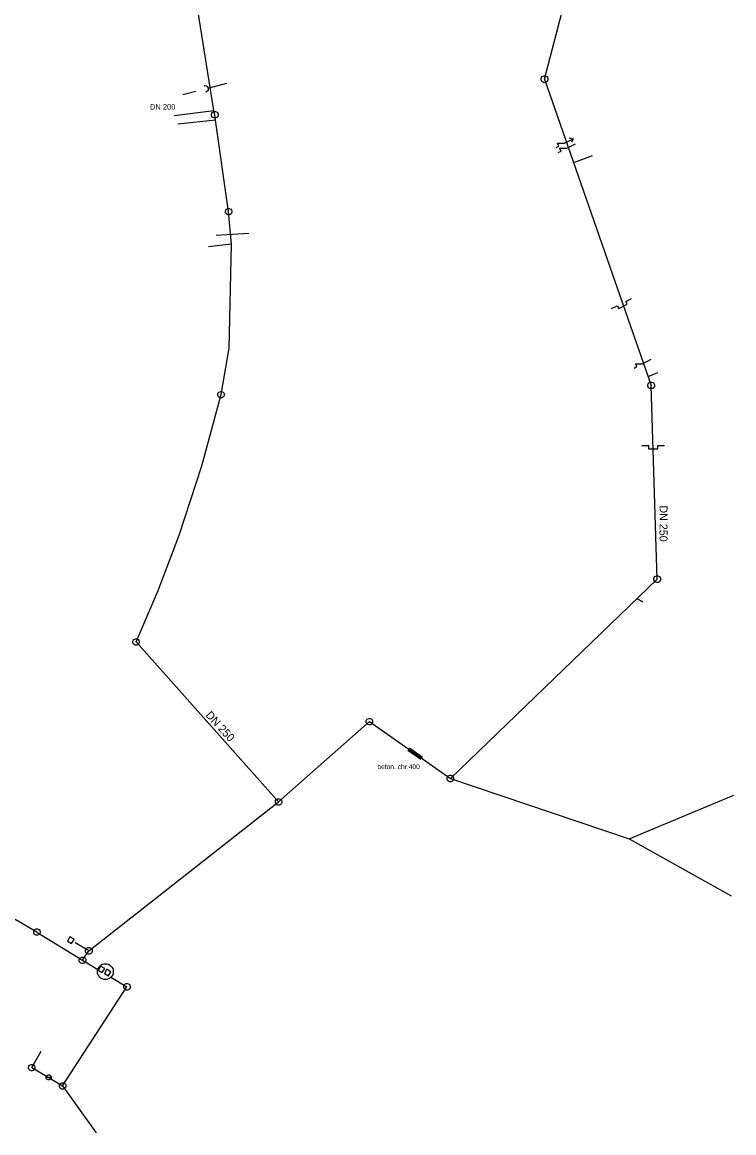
# Model space of a CAD drawing. Extents: x -717256 to -716843, y -1145423 to -1142840.
# Drawn here: x -716986 to -716875, y -1145422.6 to -1145249.2 of the extents above; entities that cross this region are included whole.
import ezdxf

# ---------------------------------------------------------------- set-up
doc = ezdxf.new("R2010")
doc.units = 0
for name, color, linetype in [('Vrstva 29', 7, 'Continuous'), ('Vrstva 30', 7, 'Continuous'), ('Vrstva 31', 7, 'Continuous'), ('Vrstva 9', 7, 'Continuous')]:
    doc.layers.add(name, color=color, linetype=linetype)

msp = doc.modelspace()

# ---------------------------------------------------------------- linework, layer by layer
at = {"layer": 'Vrstva 29'}
for p, q in [((-716923.822, -1145364.386), (-716925.867, -1145362.949)), ((-716925.579, -1145362.539), (-716923.534, -1145363.977))]:
    msp.add_line(p, q, dxfattribs=at)
at = {"layer": 'Vrstva 30'}
for p, q in [((-716956.115, -1145263.016), (-716962.169, -1145225.426)), ((-716904.513, -1145258.142), (-716897.434, -1145230.811)), ((-716905.013, -1145258.042), (-716904.963, -1145257.892)), ((-716905.013, -1145258.242), (-716905.013, -1145258.042)), ((-716904.913, -1145258.492), (-716905.013, -1145258.242)), ((-716904.963, -1145257.892), (-716904.863, -1145257.742)), ((-716904.863, -1145257.742), (-716904.613, -1145257.642)), ((-716904.613, -1145257.642), (-716904.413, -1145257.642)), ((-716904.513, -1145258.142), (-716887.864, -1145305.962)), ((-716904.413, -1145257.642), (-716904.163, -1145257.742)), ((-716904.163, -1145257.742), (-716904.063, -1145257.892)), ((-716904.013, -1145258.242), (-716904.113, -1145258.492)), ((-716904.063, -1145257.892), (-716904.013, -1145258.042)), ((-716904.013, -1145258.042), (-716904.013, -1145258.242)), ((-716904.763, -1145258.592), (-716904.913, -1145258.492)), ((-716904.613, -1145258.642), (-716904.763, -1145258.592)), ((-716904.413, -1145258.642), (-716904.613, -1145258.642)), ((-716904.263, -1145258.592), (-716904.413, -1145258.642)), ((-716904.113, -1145258.492), (-716904.263, -1145258.592)), ((-716956.47, -1145263.599), (-716956.42, -1145263.449)), ((-716956.47, -1145263.799), (-716956.47, -1145263.599)), ((-716956.42, -1145263.449), (-716956.32, -1145263.299)), ((-716956.32, -1145263.299), (-716956.07, -1145263.199)), ((-716955.97, -1145263.699), (-716956.115, -1145263.016)), ((-716956.07, -1145263.199), (-716955.87, -1145263.199)), ((-716955.87, -1145263.199), (-716955.62, -1145263.299)), ((-716955.62, -1145263.299), (-716955.52, -1145263.449)), ((-716955.52, -1145263.449), (-716955.47, -1145263.599)), ((-716955.47, -1145263.599), (-716955.47, -1145263.799)), ((-716956.37, -1145264.049), (-716956.47, -1145263.799)), ((-716956.22, -1145264.149), (-716956.37, -1145264.049)), ((-716956.07, -1145264.199), (-716956.22, -1145264.149)), ((-716955.87, -1145264.199), (-716956.07, -1145264.199)), ((-716955.891, -1145264.537), (-716955.97, -1145263.699)), ((-716953.814, -1145278.818), (-716955.891, -1145264.537)), ((-716955.72, -1145264.149), (-716955.87, -1145264.199)), ((-716955.57, -1145264.049), (-716955.72, -1145264.149)), ((-716955.47, -1145263.799), (-716955.57, -1145264.049)), ((-716954.314, -1145278.718), (-716954.264, -1145278.568)), ((-716954.314, -1145278.918), (-716954.314, -1145278.718)), ((-716954.214, -1145279.168), (-716954.314, -1145278.918)), ((-716954.264, -1145278.568), (-716954.164, -1145278.418)), ((-716954.064, -1145279.268), (-716954.214, -1145279.168)), ((-716954.164, -1145278.418), (-716953.914, -1145278.318)), ((-716953.914, -1145278.318), (-716953.714, -1145278.318)), ((-716953.374, -1145283.917), (-716953.814, -1145278.818)), ((-716953.714, -1145278.318), (-716953.464, -1145278.418)), ((-716953.414, -1145279.168), (-716953.564, -1145279.268)), ((-716953.464, -1145278.418), (-716953.364, -1145278.568)), ((-716953.314, -1145278.918), (-716953.414, -1145279.168)), ((-716953.364, -1145278.568), (-716953.314, -1145278.718)), ((-716953.314, -1145278.718), (-716953.314, -1145278.918)), ((-716953.914, -1145279.318), (-716954.064, -1145279.268)), ((-716953.714, -1145279.318), (-716953.914, -1145279.318)), ((-716953.564, -1145279.268), (-716953.714, -1145279.318)), ((-716953.738, -1145300.138), (-716953.374, -1145283.917)), ((-716954.999, -1145307.385), (-716953.738, -1145300.138)), ((-716955.449, -1145307.135), (-716955.349, -1145306.985)), ((-716955.349, -1145306.985), (-716955.099, -1145306.885)), ((-716955.099, -1145306.885), (-716954.899, -1145306.885)), ((-716954.899, -1145306.885), (-716954.649, -1145306.985)), ((-716954.649, -1145306.985), (-716954.549, -1145307.135)), ((-716888.364, -1145305.862), (-716888.314, -1145305.712)), ((-716888.364, -1145306.062), (-716888.364, -1145305.862)), ((-716888.264, -1145306.312), (-716888.364, -1145306.062)), ((-716888.314, -1145305.712), (-716888.214, -1145305.562)), ((-716888.114, -1145306.412), (-716888.264, -1145306.312)), ((-716888.214, -1145305.562), (-716887.964, -1145305.462)), ((-716887.964, -1145306.462), (-716888.114, -1145306.412)), ((-716887.964, -1145305.462), (-716887.764, -1145305.462)), ((-716887.764, -1145306.462), (-716887.964, -1145306.462)), ((-716886.933, -1145336.203), (-716887.864, -1145305.962)), ((-716887.764, -1145305.462), (-716887.514, -1145305.562)), ((-716887.614, -1145306.412), (-716887.764, -1145306.462)), ((-716887.464, -1145306.312), (-716887.614, -1145306.412)), ((-716887.514, -1145305.562), (-716887.414, -1145305.712)), ((-716887.364, -1145306.062), (-716887.464, -1145306.312)), ((-716887.414, -1145305.712), (-716887.364, -1145305.862)), ((-716887.364, -1145305.862), (-716887.364, -1145306.062)), ((-716957.99, -1145318.53), (-716954.999, -1145307.385)), ((-716955.499, -1145307.285), (-716955.449, -1145307.135)), ((-716955.499, -1145307.485), (-716955.499, -1145307.285)), ((-716955.399, -1145307.735), (-716955.499, -1145307.485)), ((-716955.249, -1145307.835), (-716955.399, -1145307.735)), ((-716955.099, -1145307.885), (-716955.249, -1145307.835)), ((-716954.899, -1145307.885), (-716955.099, -1145307.885)), ((-716954.749, -1145307.835), (-716954.899, -1145307.885)), ((-716954.599, -1145307.735), (-716954.749, -1145307.835)), ((-716954.499, -1145307.485), (-716954.599, -1145307.735)), ((-716954.549, -1145307.135), (-716954.499, -1145307.285)), ((-716954.499, -1145307.285), (-716954.499, -1145307.485)), ((-716961.557, -1145329.322), (-716957.99, -1145318.53)), ((-716964.822, -1145337.99), (-716961.557, -1145329.322)), ((-716919.208, -1145367.324), (-716886.933, -1145336.203)), ((-716887.433, -1145336.103), (-716887.383, -1145335.953)), ((-716887.433, -1145336.303), (-716887.433, -1145336.103)), ((-716887.333, -1145336.553), (-716887.433, -1145336.303)), ((-716887.383, -1145335.953), (-716887.283, -1145335.803)), ((-716887.283, -1145335.803), (-716887.033, -1145335.703)), ((-716887.033, -1145335.703), (-716886.833, -1145335.703)), ((-716886.833, -1145335.703), (-716886.583, -1145335.803)), ((-716886.583, -1145335.803), (-716886.483, -1145335.953)), ((-716886.433, -1145336.303), (-716886.533, -1145336.553)), ((-716886.483, -1145335.953), (-716886.433, -1145336.103)), ((-716886.433, -1145336.103), (-716886.433, -1145336.303)), ((-716968.267, -1145346.012), (-716964.822, -1145337.99)), ((-716887.183, -1145336.653), (-716887.333, -1145336.553)), ((-716887.033, -1145336.703), (-716887.183, -1145336.653)), ((-716886.833, -1145336.703), (-716887.033, -1145336.703)), ((-716886.683, -1145336.653), (-716886.833, -1145336.703)), ((-716886.533, -1145336.553), (-716886.683, -1145336.653)), ((-716968.767, -1145345.912), (-716968.717, -1145345.762)), ((-716968.767, -1145346.112), (-716968.767, -1145345.912)), ((-716968.667, -1145346.362), (-716968.767, -1145346.112)), ((-716968.717, -1145345.762), (-716968.617, -1145345.612)), ((-716968.517, -1145346.462), (-716968.667, -1145346.362)), ((-716968.617, -1145345.612), (-716968.367, -1145345.512)), ((-716968.367, -1145346.512), (-716968.517, -1145346.462)), ((-716968.367, -1145345.512), (-716968.167, -1145345.512)), ((-716968.167, -1145346.512), (-716968.367, -1145346.512)), ((-716968.267, -1145346.012), (-716946.027, -1145370.989)), ((-716968.167, -1145345.512), (-716967.917, -1145345.612)), ((-716968.017, -1145346.462), (-716968.167, -1145346.512)), ((-716967.867, -1145346.362), (-716968.017, -1145346.462)), ((-716967.917, -1145345.612), (-716967.817, -1145345.762)), ((-716967.767, -1145346.112), (-716967.867, -1145346.362)), ((-716967.817, -1145345.762), (-716967.767, -1145345.912)), ((-716967.767, -1145345.912), (-716967.767, -1145346.112)), ((-716946.027, -1145370.989), (-716931.84, -1145358.444)), ((-716932.34, -1145358.344), (-716932.29, -1145358.194)), ((-716932.34, -1145358.544), (-716932.34, -1145358.344)), ((-716932.24, -1145358.794), (-716932.34, -1145358.544)), ((-716932.29, -1145358.194), (-716932.19, -1145358.044)), ((-716932.09, -1145358.894), (-716932.24, -1145358.794)), ((-716932.19, -1145358.044), (-716931.94, -1145357.944)), ((-716931.94, -1145358.944), (-716932.09, -1145358.894)), ((-716931.94, -1145357.944), (-716931.74, -1145357.944)), ((-716931.74, -1145358.944), (-716931.94, -1145358.944)), ((-716931.84, -1145358.444), (-716919.208, -1145367.324)), ((-716931.74, -1145357.944), (-716931.49, -1145358.044)), ((-716931.59, -1145358.894), (-716931.74, -1145358.944)), ((-716931.44, -1145358.794), (-716931.59, -1145358.894)), ((-716931.49, -1145358.044), (-716931.39, -1145358.194)), ((-716931.34, -1145358.544), (-716931.44, -1145358.794)), ((-716931.39, -1145358.194), (-716931.34, -1145358.344)), ((-716931.34, -1145358.344), (-716931.34, -1145358.544)), ((-716919.708, -1145367.224), (-716919.658, -1145367.074)), ((-716919.708, -1145367.424), (-716919.708, -1145367.224)), ((-716919.608, -1145367.674), (-716919.708, -1145367.424)), ((-716919.658, -1145367.074), (-716919.558, -1145366.924)), ((-716919.458, -1145367.774), (-716919.608, -1145367.674)), ((-716919.558, -1145366.924), (-716919.308, -1145366.824)), ((-716919.308, -1145366.824), (-716919.108, -1145366.824)), ((-716919.108, -1145366.824), (-716918.858, -1145366.924)), ((-716918.808, -1145367.674), (-716918.958, -1145367.774)), ((-716918.858, -1145366.924), (-716918.758, -1145367.074)), ((-716918.708, -1145367.424), (-716918.808, -1145367.674)), ((-716918.758, -1145367.074), (-716918.708, -1145367.224)), ((-716918.708, -1145367.224), (-716918.708, -1145367.424)), ((-716919.308, -1145367.824), (-716919.458, -1145367.774)), ((-716919.108, -1145367.824), (-716919.308, -1145367.824)), ((-716918.958, -1145367.774), (-716919.108, -1145367.824)), ((-716975.639, -1145394.238), (-716946.027, -1145370.989)), ((-716946.527, -1145370.889), (-716946.477, -1145370.739)), ((-716946.527, -1145371.089), (-716946.527, -1145370.889)), ((-716946.427, -1145371.339), (-716946.527, -1145371.089)), ((-716946.477, -1145370.739), (-716946.377, -1145370.589)), ((-716946.377, -1145370.589), (-716946.127, -1145370.489)), ((-716946.127, -1145370.489), (-716945.927, -1145370.489)), ((-716945.927, -1145370.489), (-716945.677, -1145370.589)), ((-716945.677, -1145370.589), (-716945.577, -1145370.739)), ((-716945.527, -1145371.089), (-716945.627, -1145371.339)), ((-716945.577, -1145370.739), (-716945.527, -1145370.889)), ((-716945.527, -1145370.889), (-716945.527, -1145371.089)), ((-716946.277, -1145371.439), (-716946.427, -1145371.339)), ((-716946.127, -1145371.489), (-716946.277, -1145371.439)), ((-716945.927, -1145371.489), (-716946.127, -1145371.489)), ((-716945.777, -1145371.439), (-716945.927, -1145371.489)), ((-716945.627, -1145371.339), (-716945.777, -1145371.439)), ((-716983.743, -1145391.3), (-716987.118, -1145389.33)), ((-716984.243, -1145391.2), (-716984.193, -1145391.05)), ((-716984.243, -1145391.4), (-716984.243, -1145391.2)), ((-716984.143, -1145391.65), (-716984.243, -1145391.4)), ((-716984.193, -1145391.05), (-716984.093, -1145390.9)), ((-716983.993, -1145391.75), (-716984.143, -1145391.65)), ((-716984.093, -1145390.9), (-716983.843, -1145390.8)), ((-716983.843, -1145391.8), (-716983.993, -1145391.75)), ((-716983.843, -1145390.8), (-716983.643, -1145390.8)), ((-716983.643, -1145391.8), (-716983.843, -1145391.8)), ((-716983.743, -1145391.3), (-716976.619, -1145395.707)), ((-716983.643, -1145390.8), (-716983.393, -1145390.9)), ((-716983.493, -1145391.75), (-716983.643, -1145391.8)), ((-716983.343, -1145391.65), (-716983.493, -1145391.75)), ((-716983.393, -1145390.9), (-716983.293, -1145391.05)), ((-716983.243, -1145391.4), (-716983.343, -1145391.65)), ((-716983.293, -1145391.05), (-716983.243, -1145391.2)), ((-716983.243, -1145391.2), (-716983.243, -1145391.4)), ((-716978.591, -1145392.071), (-716978.973, -1145392.716)), ((-716978.973, -1145392.716), (-716978.327, -1145393.098)), ((-716977.945, -1145392.452), (-716978.591, -1145392.071)), ((-716978.327, -1145393.098), (-716977.945, -1145392.452)), ((-716975.639, -1145394.238), (-716977.784, -1145392.977)), ((-716977.069, -1145395.457), (-716976.969, -1145395.307)), ((-716976.969, -1145395.307), (-716976.719, -1145395.207)), ((-716976.719, -1145395.207), (-716976.519, -1145395.207)), ((-716976.619, -1145395.707), (-716975.639, -1145394.238)), ((-716976.519, -1145395.207), (-716976.269, -1145395.307)), ((-716976.269, -1145395.307), (-716976.169, -1145395.457)), ((-716976.139, -1145394.138), (-716976.089, -1145393.988)), ((-716976.139, -1145394.338), (-716976.139, -1145394.138)), ((-716976.039, -1145394.588), (-716976.139, -1145394.338)), ((-716976.089, -1145393.988), (-716975.989, -1145393.838)), ((-716975.889, -1145394.688), (-716976.039, -1145394.588)), ((-716975.989, -1145393.838), (-716975.739, -1145393.738)), ((-716975.739, -1145394.738), (-716975.889, -1145394.688)), ((-716975.739, -1145393.738), (-716975.539, -1145393.738)), ((-716975.539, -1145394.738), (-716975.739, -1145394.738)), ((-716975.539, -1145393.738), (-716975.289, -1145393.838)), ((-716975.389, -1145394.688), (-716975.539, -1145394.738)), ((-716975.239, -1145394.588), (-716975.389, -1145394.688)), ((-716975.289, -1145393.838), (-716975.189, -1145393.988)), ((-716975.139, -1145394.338), (-716975.239, -1145394.588)), ((-716975.189, -1145393.988), (-716975.139, -1145394.138)), ((-716975.139, -1145394.138), (-716975.139, -1145394.338)), ((-716977.119, -1145395.607), (-716977.069, -1145395.457)), ((-716977.119, -1145395.807), (-716977.119, -1145395.607)), ((-716977.019, -1145396.057), (-716977.119, -1145395.807)), ((-716976.869, -1145396.157), (-716977.019, -1145396.057)), ((-716976.719, -1145396.207), (-716976.869, -1145396.157)), ((-716976.519, -1145396.207), (-716976.719, -1145396.207)), ((-716976.619, -1145395.707), (-716974.238, -1145397.13)), ((-716976.369, -1145396.157), (-716976.519, -1145396.207)), ((-716976.219, -1145396.057), (-716976.369, -1145396.157)), ((-716976.119, -1145395.807), (-716976.219, -1145396.057)), ((-716976.169, -1145395.457), (-716976.119, -1145395.607)), ((-716976.119, -1145395.607), (-716976.119, -1145395.807)), ((-716973.803, -1145396.616), (-716974.185, -1145397.261)), ((-716973.158, -1145396.997), (-716973.803, -1145396.616)), ((-716973.539, -1145397.643), (-716973.158, -1145396.997)), ((-716972.835, -1145397.106), (-716973.216, -1145397.751)), ((-716972.189, -1145397.487), (-716972.835, -1145397.106)), ((-716974.185, -1145397.261), (-716973.539, -1145397.643)), ((-716973.216, -1145397.751), (-716972.571, -1145398.133)), ((-716972.571, -1145398.133), (-716972.189, -1145397.487)), ((-716972.182, -1145398.359), (-716969.683, -1145399.852)), ((-716979.727, -1145415.324), (-716969.683, -1145399.852)), ((-716970.183, -1145399.752), (-716970.133, -1145399.602)), ((-716970.183, -1145399.952), (-716970.183, -1145399.752)), ((-716970.083, -1145400.202), (-716970.183, -1145399.952)), ((-716970.133, -1145399.602), (-716970.033, -1145399.452)), ((-716969.933, -1145400.302), (-716970.083, -1145400.202)), ((-716970.033, -1145399.452), (-716969.783, -1145399.352)), ((-716969.783, -1145400.352), (-716969.933, -1145400.302)), ((-716969.783, -1145399.352), (-716969.583, -1145399.352)), ((-716969.583, -1145400.352), (-716969.783, -1145400.352)), ((-716969.583, -1145399.352), (-716969.333, -1145399.452)), ((-716969.433, -1145400.302), (-716969.583, -1145400.352)), ((-716969.283, -1145400.202), (-716969.433, -1145400.302)), ((-716969.333, -1145399.452), (-716969.233, -1145399.602)), ((-716969.183, -1145399.952), (-716969.283, -1145400.202)), ((-716969.233, -1145399.602), (-716969.183, -1145399.752)), ((-716969.183, -1145399.752), (-716969.183, -1145399.952)), ((-716984.557, -1145412.466), (-716983.073, -1145409.883)), ((-716985.057, -1145412.366), (-716985.007, -1145412.216)), ((-716985.057, -1145412.566), (-716985.057, -1145412.366)), ((-716984.957, -1145412.816), (-716985.057, -1145412.566)), ((-716985.007, -1145412.216), (-716984.907, -1145412.066)), ((-716984.907, -1145412.066), (-716984.657, -1145411.966)), ((-716984.657, -1145411.966), (-716984.457, -1145411.966)), ((-716984.557, -1145412.466), (-716981.897, -1145413.99)), ((-716984.457, -1145411.966), (-716984.207, -1145412.066)), ((-716984.207, -1145412.066), (-716984.107, -1145412.216)), ((-716984.057, -1145412.566), (-716984.157, -1145412.816)), ((-716984.107, -1145412.216), (-716984.057, -1145412.366)), ((-716984.057, -1145412.366), (-716984.057, -1145412.566)), ((-716984.807, -1145412.916), (-716984.957, -1145412.816)), ((-716984.657, -1145412.966), (-716984.807, -1145412.916)), ((-716984.457, -1145412.966), (-716984.657, -1145412.966)), ((-716984.307, -1145412.916), (-716984.457, -1145412.966)), ((-716984.157, -1145412.816), (-716984.307, -1145412.916)), ((-716982.297, -1145413.89), (-716982.197, -1145413.69)), ((-716982.297, -1145414.09), (-716982.297, -1145413.89)), ((-716981.497, -1145413.99), (-716982.297, -1145413.99)), ((-716982.197, -1145414.29), (-716982.297, -1145414.09)), ((-716982.197, -1145413.69), (-716981.997, -1145413.59)), ((-716981.997, -1145414.39), (-716982.197, -1145414.29)), ((-716981.997, -1145413.59), (-716981.797, -1145413.59)), ((-716981.797, -1145414.39), (-716981.997, -1145414.39)), ((-716981.897, -1145413.99), (-716979.727, -1145415.324)), ((-716981.797, -1145413.59), (-716981.597, -1145413.69)), ((-716981.597, -1145414.29), (-716981.797, -1145414.39)), ((-716981.597, -1145413.69), (-716981.497, -1145413.89)), ((-716981.497, -1145414.09), (-716981.597, -1145414.29)), ((-716981.497, -1145413.89), (-716981.497, -1145414.09)), ((-716980.227, -1145415.224), (-716980.177, -1145415.074)), ((-716980.227, -1145415.424), (-716980.227, -1145415.224)), ((-716980.127, -1145415.674), (-716980.227, -1145415.424)), ((-716980.177, -1145415.074), (-716980.077, -1145414.924)), ((-716979.977, -1145415.774), (-716980.127, -1145415.674)), ((-716980.077, -1145414.924), (-716979.827, -1145414.824)), ((-716979.827, -1145415.824), (-716979.977, -1145415.774)), ((-716979.827, -1145414.824), (-716979.627, -1145414.824)), ((-716979.627, -1145415.824), (-716979.827, -1145415.824)), ((-716979.727, -1145415.324), (-716974.514, -1145422.643)), ((-716979.627, -1145414.824), (-716979.377, -1145414.924)), ((-716979.477, -1145415.774), (-716979.627, -1145415.824)), ((-716979.327, -1145415.674), (-716979.477, -1145415.774)), ((-716979.377, -1145414.924), (-716979.277, -1145415.074)), ((-716979.227, -1145415.424), (-716979.327, -1145415.674)), ((-716979.277, -1145415.074), (-716979.227, -1145415.224)), ((-716979.227, -1145415.224), (-716979.227, -1145415.424))]:
    msp.add_line(p, q, dxfattribs=at)
msp.add_circle((-716973.054, -1145397.481), 1.238, dxfattribs=at)
at = {"layer": 'Vrstva 31'}
for p, q in [((-716962.315, -1145263.793), (-716956.115, -1145263.016)), ((-716955.891, -1145264.537), (-716961.768, -1145265.175)), ((-716899.934, -1145271.162), (-716897.044, -1145270.083)), ((-716953.374, -1145283.917), (-716956.935, -1145284.3)), ((-716888.354, -1145304.576), (-716886.811, -1145303.956)), ((-716890.04, -1145339.199), (-716889.153, -1145339.749)), ((-716919.208, -1145367.324), (-716891.279, -1145376.733)), ((-716891.279, -1145376.733), (-716874.975, -1145369.917)), ((-716891.279, -1145376.733), (-716875.379, -1145385.666))]:
    msp.add_line(p, q, dxfattribs=at)
at = {"layer": 'Vrstva 9'}
for p, q in [((-716960.961, -1145260.55), (-716958.955, -1145260.027)), ((-716957.63, -1145259.165), (-716957.533, -1145259.14)), ((-716957.533, -1145259.14), (-716957.266, -1145259.174)), ((-716957.281, -1145260.108), (-716957.378, -1145260.133)), ((-716957.148, -1145260.022), (-716957.281, -1145260.108)), ((-716957.266, -1145259.174), (-716957.131, -1145259.294)), ((-716957.028, -1145259.887), (-716957.148, -1145260.022)), ((-716957.131, -1145259.294), (-716957.045, -1145259.426)), ((-716957.045, -1145259.426), (-716956.995, -1145259.62)), ((-716956.995, -1145259.62), (-716957.028, -1145259.887)), ((-716957.02, -1145259.523), (-716954.117, -1145258.767)), ((-716902.713, -1145268.807), (-716902.268, -1145268.58)), ((-716902.495, -1145268.135), (-716901.377, -1145268.126)), ((-716902.268, -1145268.58), (-716902.495, -1145268.135)), ((-716901.377, -1145268.126), (-716900.04, -1145267.445)), ((-716901.035, -1145268.929), (-716899.699, -1145268.248)), ((-716900.667, -1145267.316), (-716900.04, -1145267.445)), ((-716900.04, -1145267.445), (-716900.304, -1145268.029)), ((-716902.372, -1145269.61), (-716901.926, -1145269.383)), ((-716902.153, -1145268.938), (-716901.035, -1145268.929)), ((-716901.926, -1145269.383), (-716902.153, -1145268.938)), ((-716955.78, -1145282.51), (-716950.655, -1145282.182)), ((-716891.826, -1145292.833), (-716890.935, -1145292.379)), ((-716891.599, -1145293.278), (-716891.826, -1145292.833)), ((-716894.054, -1145293.968), (-716893.163, -1145293.514)), ((-716893.163, -1145293.514), (-716892.936, -1145293.959)), ((-716892.936, -1145293.959), (-716891.599, -1145293.278)), ((-716890.544, -1145303.245), (-716890.099, -1145303.018)), ((-716890.326, -1145302.573), (-716889.208, -1145302.564)), ((-716890.099, -1145303.018), (-716890.326, -1145302.573)), ((-716889.208, -1145302.564), (-716887.871, -1145301.883)), ((-716889.304, -1145315.354), (-716888.304, -1145315.354)), ((-716888.304, -1145315.354), (-716888.304, -1145315.854)), ((-716886.804, -1145315.854), (-716886.804, -1145315.354)), ((-716886.804, -1145315.354), (-716885.804, -1145315.354)), ((-716888.304, -1145315.854), (-716886.804, -1145315.854))]:
    msp.add_line(p, q, dxfattribs=at)

# ---------------------------------------------------------------- texts
at = {"layer": 'Vrstva 30'}
for rotation, p in [(270, (-716886.564, -1145324.685)), (312.3, (-716957.491, -1145357.5))]:
    msp.add_text('DN 250', height=1.25, rotation=rotation, dxfattribs=at).set_placement(p)
msp.add_text('beton. chr.400', height=0.74999, dxfattribs=at).set_placement((-716930.597, -1145365.864))
at = {"layer": 'Vrstva 31'}
msp.add_text('DN 200', height=0.85, dxfattribs=at).set_placement((-716966.106, -1145262.887))

doc.saveas('drawing.dxf')
